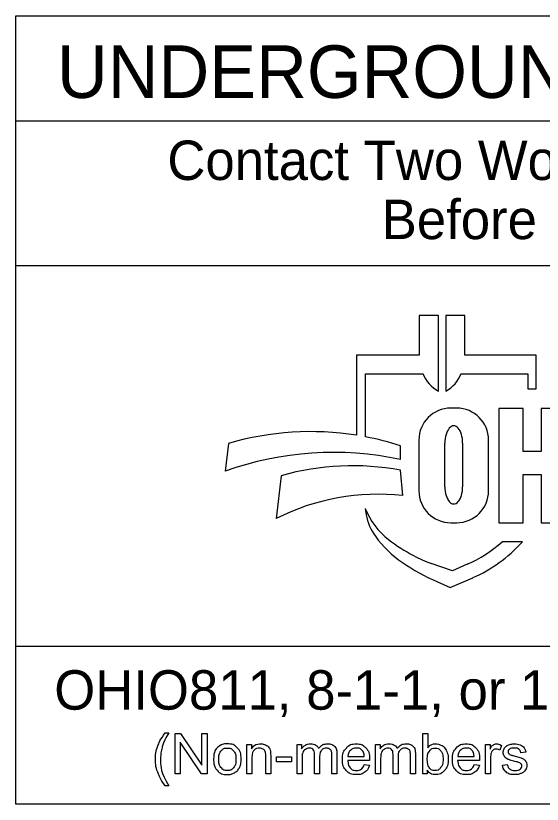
# Model space of a CAD drawing. Extents: x 1862092.2 to 1862141.4, y 420599.8 to 420643.6.
# Drawn here: x 1862100.205 to 1862102.209, y 420603.351 to 420606.351 of the extents above; entities that cross this region are included whole.
import ezdxf

# ---------------------------------------------------------------- set-up
doc = ezdxf.new("R2010")
doc.units = 0
doc.layers.add('SH_Data', color=7, linetype='Continuous')

msp = doc.modelspace()

# ---------------------------------------------------------------- linework, layer by layer
at = {"layer": 'SH_Data'}
for p, q in [((1862100.2055, 420606.3508), (1862104.9554, 420606.3508)), ((1862100.2055, 420603.3508), (1862100.2055, 420606.3508)), ((1862100.2055, 420605.9508), (1862104.9554, 420605.9508)), ((1862100.2055, 420605.4008), (1862104.9554, 420605.4008)), ((1862101.8136, 420605.2103), (1862101.7408, 420605.2103)), ((1862101.7408, 420605.2103), (1862101.7408, 420605.0589)), ((1862101.8136, 420604.9223), (1862101.8136, 420605.2103)), ((1862101.9147, 420605.2103), (1862101.8419, 420605.2103)), ((1862101.8419, 420605.2103), (1862101.8419, 420604.9223)), ((1862101.9147, 420605.0589), (1862101.9147, 420605.2103)), ((1862101.7408, 420605.0589), (1862101.5018, 420605.0589)), ((1862101.5018, 420605.0589), (1862101.5018, 420604.7548)), ((1862102.1853, 420605.0589), (1862101.9147, 420605.0589)), ((1862102.1853, 420604.9315), (1862102.1853, 420605.0589)), ((1862101.5361, 420604.7489), (1862101.5361, 420604.989)), ((1862101.5361, 420604.989), (1862101.7549, 420604.989)), ((1862101.9006, 420604.989), (1862102.1537, 420604.989)), ((1862102.1537, 420604.989), (1862102.1537, 420604.9315)), ((1862102.1537, 420604.9315), (1862102.1853, 420604.9315)), ((1862101.8833, 420604.8578), (1862101.8609, 420604.8578)), ((1862102.136, 420604.8564), (1862102.0437, 420604.8564)), ((1862102.0437, 420604.8564), (1862102.0437, 420604.4219)), ((1862101.7394, 420604.7363), (1862101.7394, 420604.5434)), ((1862102.0048, 420604.5434), (1862102.0048, 420604.7363)), ((1862101.0154, 420604.7238), (1862101.0026, 420604.6176)), ((1862101.669, 420604.6622), (1862101.669, 420604.7149)), ((1862101.8384, 420604.5589), (1862101.8384, 420604.725)), ((1862101.906, 420604.725), (1862101.906, 420604.5589)), ((1862101.6781, 420604.5254), (1862101.6697, 420604.6218)), ((1862102.136, 420604.4219), (1862102.136, 420604.6056)), ((1862101.2159, 420604.6008), (1862101.196, 420604.4377)), ((1862101.5352, 420604.4766), (1862101.5394, 420604.4522)), ((1862101.8609, 420604.4219), (1862101.8833, 420604.4219)), ((1862102.0437, 420604.4219), (1862102.136, 420604.4219)), ((1862102.1338, 420604.3492), (1862102.0558, 420604.3492)), ((1862102.1316, 420604.3468), (1862102.1338, 420604.3492)), ((1862101.867, 420604.2394), (1862101.7863, 420604.2672)), ((1862101.9228, 420604.2636), (1862101.867, 420604.2394)), ((1862101.8081, 420604.1979), (1862101.8588, 420604.1755)), ((1862101.8588, 420604.1755), (1862101.9448, 420604.2128)), ((1862104.9554, 420603.9508), (1862100.2055, 420603.9508)), ((1862104.9554, 420603.3508), (1862100.2055, 420603.3508))]:
    msp.add_line(p, q, dxfattribs=at)
for points in [[(1862102.136, 420604.6056), (1862102.2052, 420604.6056), (1862102.2052, 420604.4219), (1862102.2975, 420604.4219), (1862102.2975, 420604.8564), (1862102.2052, 420604.8564), (1862102.2052, 420604.6925), (1862102.136, 420604.6925), (1862102.136, 420604.8564)], [(1862100.7744, 420603.6227), (1862100.7879, 420603.6227)], [(1862100.8121, 420603.4661), (1862100.8121, 420603.6201), (1862100.8329, 420603.6201), (1862100.914, 420603.4992), (1862100.914, 420603.6201), (1862100.9334, 420603.6201), (1862100.9334, 420603.4661), (1862100.9126, 420603.4661), (1862100.8316, 420603.5871), (1862100.8316, 420603.4661), (1862100.8121, 420603.4661)], [(1862101.7715, 420603.4661), (1862101.754, 420603.4661), (1862101.754, 420603.6201), (1862101.7729, 420603.6201), (1862101.7729, 420603.5652)], [(1862101.0849, 420603.4661), (1862101.0849, 420603.5777), (1862101.1019, 420603.5777), (1862101.1019, 420603.5619)], [(1862101.2761, 420603.4661), (1862101.2761, 420603.5777), (1862101.293, 420603.5777), (1862101.293, 420603.562)], [(1862101.5749, 420603.4661), (1862101.5749, 420603.5777), (1862101.5918, 420603.5777), (1862101.5918, 420603.562)], [(1862101.9931, 420603.4661), (1862101.9931, 420603.5777), (1862102.0102, 420603.5777), (1862102.0102, 420603.5608)], [(1862102.0537, 420603.5742), (1862102.0471, 420603.5567)], [(1862101.1038, 420603.527), (1862101.1038, 420603.4661), (1862101.0849, 420603.4661)], [(1862101.1755, 420603.5347), (1862101.1755, 420603.4661), (1862101.1566, 420603.4661), (1862101.1566, 420603.534)], [(1862101.197, 420603.5124), (1862101.197, 420603.5314), (1862101.2552, 420603.5314), (1862101.2552, 420603.5124), (1862101.197, 420603.5124)], [(1862101.3613, 420603.5309), (1862101.3613, 420603.4661), (1862101.3424, 420603.4661), (1862101.3424, 420603.5386)], [(1862101.4274, 420603.5427), (1862101.4274, 420603.4661), (1862101.4085, 420603.4661), (1862101.4085, 420603.5364)], [(1862101.4695, 420603.5326), (1862101.5318, 420603.5326)], [(1862101.6601, 420603.5309), (1862101.6601, 420603.4661), (1862101.6412, 420603.4661), (1862101.6412, 420603.5386)], [(1862101.7262, 420603.5427), (1862101.7262, 420603.4661), (1862101.7073, 420603.4661), (1862101.7073, 420603.5364)], [(1862101.888, 420603.5326), (1862101.9503, 420603.5326)], [(1862102.146, 420603.5489), (1862102.1274, 420603.5464)], [(1862101.2949, 420603.524), (1862101.2949, 420603.4661), (1862101.2761, 420603.4661)], [(1862101.5517, 420603.5171), (1862101.4685, 420603.5171)], [(1862101.5316, 420603.5022), (1862101.5512, 420603.4997)], [(1862101.5938, 420603.524), (1862101.5938, 420603.4661), (1862101.5749, 420603.4661)], [(1862101.9701, 420603.5171), (1862101.8869, 420603.5171)], [(1862101.9501, 420603.5022), (1862101.9696, 420603.4997)], [(1862102.012, 420603.5246), (1862102.012, 420603.4661), (1862101.9931, 420603.4661)], [(1862102.0573, 420603.4995), (1862102.076, 420603.5024)], [(1862101.7715, 420603.4801), (1862101.7715, 420603.4661)], [(1862100.7879, 420603.4208), (1862100.7744, 420603.4208)]]:
    msp.add_lwpolyline(points, dxfattribs=at)
for centre, radius, start, end in [((1862101.879, 420605.039), 0.1337, 201.9296, 240.7469), ((1862101.7765, 420605.039), 0.1337, 299.2531, 338.0704), ((1862101.8609, 420604.7363), 0.1215, 90, 180), ((1862101.8833, 420604.7363), 0.1215, 0, 90), ((1862101.3278, 420603.6562), 1.1123, 81.0007, 106.3144), ((1862101.3278, 420603.6562), 1.1123, 72.1402, 79.2074), ((1862101.4135, 420603.4782), 1.2113, 77.8238, 109.8274), ((1862101.4875, 420603.6443), 0.9943, 79.44, 105.8467), ((1862101.5853, 420603.6671), 0.8633, 83.8248, 116.8021), ((1862101.8609, 420604.5434), 0.1215, 180, 270), ((1862101.8833, 420604.5434), 0.1215, 270, 0), ((1862101.7897, 420604.5745), 0.2727, 201.0457, 232.5314), ((1862101.7312, 420604.485), 0.1947, 189.6817, 216.0884), ((1862101.9128, 420604.6173), 0.4193, 216.0884, 235.7167), ((1862102.0512, 420604.9157), 0.7025, 232.5314, 241.794), ((1862101.728, 420604.7124), 0.4892, 293.4582, 312.0712), ((1862101.728, 420604.7124), 0.5445, 293.4582, 317.8286), ((1862101.9355, 420604.7), 0.4578, 241.794, 250.9821), ((1862102.1389, 420604.949), 0.8207, 235.7167, 246.2325)]:
    msp.add_arc(centre, radius, start, end, dxfattribs=at)
for centre, start_param, end_param in [((1862101.8722, 420604.725), 4.712389, 7.853982), ((1862101.8722, 420604.5589), 1.570796, 4.712389)]:
    msp.add_ellipse(centre, major_axis=(0, 0.0657), ratio=0.514403, start_param=start_param, end_param=end_param, dxfattribs=at)
for points in [[(1862100.7744, 420603.4208), (1862100.7587, 420603.4406), (1862100.7479, 420603.467), (1862100.7371, 420603.4935), (1862100.7371, 420603.5219), (1862100.7371, 420603.5469), (1862100.7452, 420603.5698), (1862100.7546, 420603.5963), (1862100.7744, 420603.6227)], [(1862100.7879, 420603.6227), (1862100.7752, 420603.6009), (1862100.7711, 420603.5915), (1862100.7647, 420603.577), (1862100.7611, 420603.5613), (1862100.7566, 420603.5416), (1862100.7566, 420603.5218), (1862100.7566, 420603.4712), (1862100.7879, 420603.4208)], [(1862100.9582, 420603.5219), (1862100.9582, 420603.5529), (1862100.9754, 420603.5678), (1862100.9898, 420603.5802), (1862101.0105, 420603.5802), (1862101.0335, 420603.5802), (1862101.0481, 420603.5651), (1862101.0627, 420603.5501), (1862101.0627, 420603.5235), (1862101.0627, 420603.502), (1862101.0562, 420603.4896), (1862101.0498, 420603.4773), (1862101.0374, 420603.4705), (1862101.0251, 420603.4637), (1862101.0105, 420603.4637), (1862100.9871, 420603.4637), (1862100.9726, 420603.4787), (1862100.9582, 420603.4937), (1862100.9582, 420603.5219)], [(1862100.9777, 420603.5219), (1862100.9777, 420603.5005), (1862100.987, 420603.4898), (1862100.9963, 420603.4791), (1862101.0105, 420603.4791), (1862101.0245, 420603.4791), (1862101.0339, 420603.4899), (1862101.0432, 420603.5006), (1862101.0432, 420603.5226), (1862101.0432, 420603.5433), (1862101.0338, 420603.5539), (1862101.0244, 420603.5646), (1862101.0105, 420603.5646), (1862100.9963, 420603.5646), (1862100.987, 420603.554), (1862100.9777, 420603.5434), (1862100.9777, 420603.5219)], [(1862101.1019, 420603.5619), (1862101.1142, 420603.5802), (1862101.1374, 420603.5802), (1862101.1474, 420603.5802), (1862101.1559, 420603.5766), (1862101.1643, 420603.573), (1862101.1685, 420603.5671), (1862101.1727, 420603.5612), (1862101.1744, 420603.5531), (1862101.1755, 420603.5479), (1862101.1755, 420603.5347)], [(1862101.1566, 420603.534), (1862101.1566, 420603.5455), (1862101.1544, 420603.5512), (1862101.1522, 420603.557), (1862101.1466, 420603.5604), (1862101.1409, 420603.5638), (1862101.1334, 420603.5638), (1862101.1213, 420603.5638), (1862101.1125, 420603.5561), (1862101.1038, 420603.5484), (1862101.1038, 420603.527)], [(1862101.293, 420603.562), (1862101.2982, 420603.5702), (1862101.3069, 420603.5752), (1862101.3157, 420603.5802), (1862101.3268, 420603.5802), (1862101.3392, 420603.5802), (1862101.3471, 420603.5751), (1862101.3551, 420603.5699), (1862101.3583, 420603.5606), (1862101.3716, 420603.5802), (1862101.3928, 420603.5802), (1862101.4095, 420603.5802), (1862101.4184, 420603.571), (1862101.4274, 420603.5618), (1862101.4274, 420603.5427)], [(1862101.3424, 420603.5386), (1862101.3424, 420603.5512), (1862101.3377, 420603.5575), (1862101.3331, 420603.5638), (1862101.3226, 420603.5638), (1862101.3146, 420603.5638), (1862101.3078, 420603.5596), (1862101.301, 420603.5554), (1862101.298, 420603.5473), (1862101.2949, 420603.5392), (1862101.2949, 420603.524)], [(1862101.4085, 420603.5364), (1862101.4085, 420603.5477), (1862101.4066, 420603.5527), (1862101.4048, 420603.5577), (1862101.3999, 420603.5607), (1862101.3951, 420603.5638), (1862101.3886, 420603.5638), (1862101.3768, 420603.5638), (1862101.369, 420603.556), (1862101.3613, 420603.5481), (1862101.3613, 420603.5309)], [(1862101.5512, 420603.4997), (1862101.5465, 420603.4826), (1862101.534, 420603.4731), (1862101.5215, 420603.4637), (1862101.5021, 420603.4637), (1862101.4776, 420603.4637), (1862101.4633, 420603.4787), (1862101.449, 420603.4938), (1862101.449, 420603.521), (1862101.449, 420603.5491), (1862101.4635, 420603.5647), (1862101.478, 420603.5802), (1862101.5011, 420603.5802), (1862101.5234, 420603.5802), (1862101.5376, 420603.565), (1862101.5518, 420603.5497), (1862101.5518, 420603.5221), (1862101.5518, 420603.5204), (1862101.5517, 420603.5171)], [(1862101.5318, 420603.5326), (1862101.5306, 420603.5467), (1862101.5247, 420603.5538), (1862101.5156, 420603.5647), (1862101.5013, 420603.5647), (1862101.4882, 420603.5647), (1862101.4793, 420603.556), (1862101.4705, 420603.5472), (1862101.4695, 420603.5326)], [(1862101.5918, 420603.562), (1862101.5971, 420603.5702), (1862101.6058, 420603.5752), (1862101.6145, 420603.5802), (1862101.6256, 420603.5802), (1862101.638, 420603.5802), (1862101.646, 420603.5751), (1862101.6539, 420603.5699), (1862101.6572, 420603.5606), (1862101.6704, 420603.5802), (1862101.6917, 420603.5802), (1862101.7083, 420603.5802), (1862101.7173, 420603.571), (1862101.7262, 420603.5618), (1862101.7262, 420603.5427)], [(1862101.6412, 420603.5386), (1862101.6412, 420603.5512), (1862101.6366, 420603.5575), (1862101.632, 420603.5638), (1862101.6214, 420603.5638), (1862101.6135, 420603.5638), (1862101.6067, 420603.5596), (1862101.5999, 420603.5554), (1862101.5968, 420603.5473), (1862101.5938, 420603.5392), (1862101.5938, 420603.524)], [(1862101.7073, 420603.5364), (1862101.7073, 420603.5477), (1862101.7055, 420603.5527), (1862101.7036, 420603.5577), (1862101.6988, 420603.5607), (1862101.694, 420603.5638), (1862101.6874, 420603.5638), (1862101.6757, 420603.5638), (1862101.6679, 420603.556), (1862101.6601, 420603.5481), (1862101.6601, 420603.5309)], [(1862101.7713, 420603.5228), (1862101.7713, 420603.5027), (1862101.7767, 420603.4938), (1862101.7857, 420603.4791), (1862101.8009, 420603.4791), (1862101.8132, 420603.4791), (1862101.8223, 420603.4899), (1862101.8313, 420603.5007), (1862101.8313, 420603.522), (1862101.8313, 420603.5439), (1862101.8226, 420603.5543), (1862101.814, 420603.5647), (1862101.8017, 420603.5647), (1862101.7893, 420603.5647), (1862101.7803, 420603.5539), (1862101.7713, 420603.5432), (1862101.7713, 420603.5228)], [(1862101.7729, 420603.5652), (1862101.7849, 420603.5802), (1862101.8035, 420603.5802), (1862101.8138, 420603.5802), (1862101.823, 420603.5761), (1862101.8322, 420603.5719), (1862101.8381, 420603.5644), (1862101.844, 420603.5569), (1862101.8474, 420603.5463), (1862101.8508, 420603.5357), (1862101.8508, 420603.5236), (1862101.8508, 420603.4949), (1862101.8366, 420603.4793), (1862101.8224, 420603.4637), (1862101.8025, 420603.4637), (1862101.7828, 420603.4637), (1862101.7715, 420603.4801)], [(1862101.9696, 420603.4997), (1862101.965, 420603.4826), (1862101.9525, 420603.4731), (1862101.94, 420603.4637), (1862101.9206, 420603.4637), (1862101.8961, 420603.4637), (1862101.8818, 420603.4787), (1862101.8674, 420603.4938), (1862101.8674, 420603.521), (1862101.8674, 420603.5491), (1862101.8819, 420603.5647), (1862101.8964, 420603.5802), (1862101.9195, 420603.5802), (1862101.9419, 420603.5802), (1862101.9561, 420603.565), (1862101.9702, 420603.5497), (1862101.9702, 420603.5221), (1862101.9702, 420603.5204), (1862101.9701, 420603.5171)], [(1862101.9503, 420603.5326), (1862101.949, 420603.5467), (1862101.9431, 420603.5538), (1862101.9341, 420603.5647), (1862101.9197, 420603.5647), (1862101.9067, 420603.5647), (1862101.8978, 420603.556), (1862101.8889, 420603.5472), (1862101.888, 420603.5326)], [(1862102.0102, 420603.5608), (1862102.0167, 420603.5727), (1862102.0222, 420603.5764), (1862102.0277, 420603.5802), (1862102.0343, 420603.5802), (1862102.0438, 420603.5802), (1862102.0537, 420603.5742)], [(1862102.0471, 420603.5567), (1862102.0402, 420603.5607), (1862102.0333, 420603.5607), (1862102.0271, 420603.5607), (1862102.0222, 420603.557), (1862102.0173, 420603.5533), (1862102.0152, 420603.5466), (1862102.012, 420603.5365), (1862102.012, 420603.5246)], [(1862102.1274, 420603.5464), (1862102.1262, 420603.555), (1862102.1201, 420603.5599), (1862102.1141, 420603.5647), (1862102.103, 420603.5647), (1862102.09, 420603.5647), (1862102.0844, 420603.5604), (1862102.0788, 420603.5561), (1862102.0788, 420603.5503), (1862102.0788, 420603.5466), (1862102.0811, 420603.5437), (1862102.0834, 420603.5406), (1862102.0884, 420603.5386), (1862102.0912, 420603.5376), (1862102.1051, 420603.5338), (1862102.1252, 420603.5284), (1862102.1332, 420603.525), (1862102.1411, 420603.5216), (1862102.1457, 420603.5151), (1862102.1502, 420603.5086), (1862102.1502, 420603.4989), (1862102.1502, 420603.4895), (1862102.1447, 420603.4811), (1862102.1391, 420603.4728), (1862102.1287, 420603.4682), (1862102.1183, 420603.4637), (1862102.1051, 420603.4637), (1862102.0833, 420603.4637), (1862102.0719, 420603.4727), (1862102.0605, 420603.4817), (1862102.0573, 420603.4995)], [(1862102.076, 420603.5024), (1862102.0776, 420603.4911), (1862102.0848, 420603.4851), (1862102.092, 420603.4791), (1862102.105, 420603.4791), (1862102.1181, 420603.4791), (1862102.1244, 420603.4845), (1862102.1307, 420603.4898), (1862102.1307, 420603.4969), (1862102.1307, 420603.5033), (1862102.1251, 420603.507), (1862102.1212, 420603.5096), (1862102.1057, 420603.5134), (1862102.0849, 420603.5187), (1862102.0769, 420603.5225), (1862102.0688, 420603.5264), (1862102.0647, 420603.5331), (1862102.0605, 420603.5399), (1862102.0605, 420603.5481), (1862102.0605, 420603.5555), (1862102.0639, 420603.5619), (1862102.0673, 420603.5682), (1862102.0732, 420603.5724), (1862102.0777, 420603.5757), (1862102.0853, 420603.578), (1862102.0929, 420603.5802), (1862102.1017, 420603.5802), (1862102.1148, 420603.5802), (1862102.1248, 420603.5764), (1862102.1347, 420603.5726), (1862102.1394, 420603.5662), (1862102.1442, 420603.5597), (1862102.146, 420603.5489)], [(1862101.4685, 420603.5171), (1862101.4695, 420603.4987), (1862101.4789, 420603.4889), (1862101.4882, 420603.4791), (1862101.5022, 420603.4791), (1862101.5126, 420603.4791), (1862101.52, 420603.4846), (1862101.5273, 420603.4901), (1862101.5316, 420603.5022)], [(1862101.8869, 420603.5171), (1862101.888, 420603.4987), (1862101.8973, 420603.4889), (1862101.9067, 420603.4791), (1862101.9206, 420603.4791), (1862101.9311, 420603.4791), (1862101.9384, 420603.4846), (1862101.9458, 420603.4901), (1862101.9501, 420603.5022)]]:
    msp.add_open_spline(points, degree=3, dxfattribs=at)

# ---------------------------------------------------------------- texts
for s, height, p in [('UNDERGROUND UTILITIES', 0.2, (1862100.3623, 420606.0381)), ('Contact Two Working Days', 0.15, (1862100.7822, 420605.7259)), ('Before You Dig', 0.15, (1862101.5978, 420605.5009)), ('OHIO811, 8-1-1, or 1-800-362-2764', 0.15, (1862100.3519, 420603.7106))]:
    msp.add_text(s, height=height, dxfattribs=at).set_placement(p)

doc.saveas('drawing.dxf')
